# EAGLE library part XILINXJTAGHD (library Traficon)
PIN HEADER
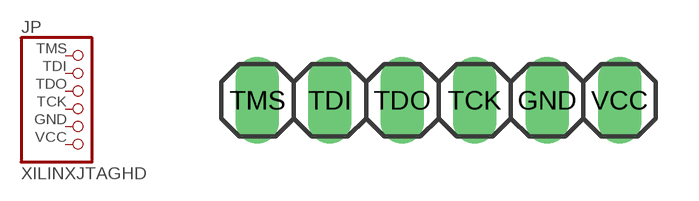
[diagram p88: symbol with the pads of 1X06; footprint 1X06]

Designator prefix JP

## XILINXJTAGHD  [1X06]
GND  5  pas
TCK  4  pas
TDI  2  pas
TDO  3  pas
TMS  1  pas
VCC  6  pas

## Footprint 1X06 (pad centres in mm)
PIN HEADER
drill 1.016 long: GND 3.81,0; TCK 1.27,0; TDI -3.81,0; TDO -1.27,0; TMS -6.35,0; VCC 6.35,0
